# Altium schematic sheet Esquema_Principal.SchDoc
size A4
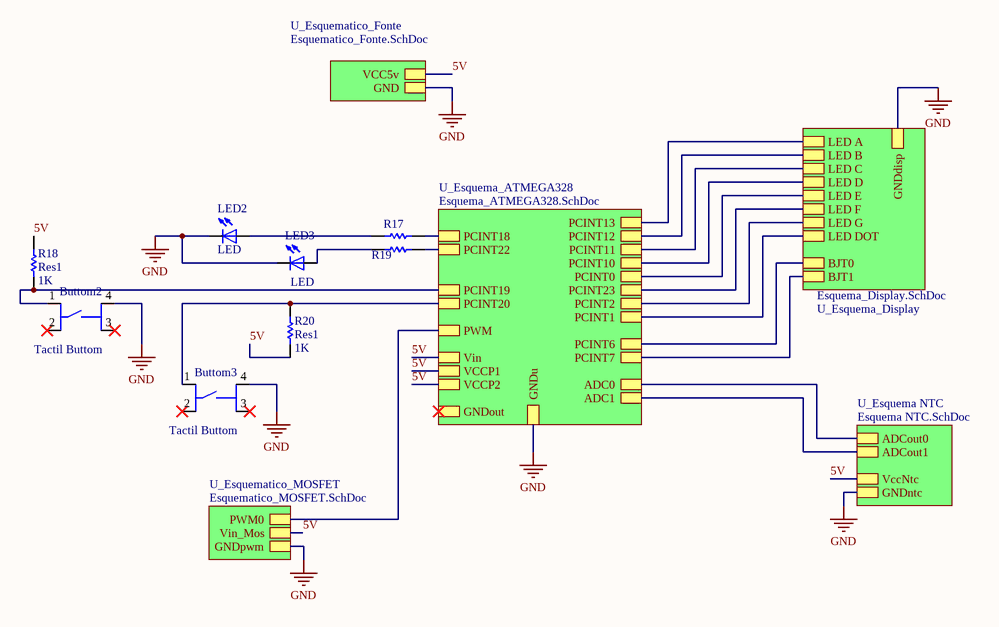
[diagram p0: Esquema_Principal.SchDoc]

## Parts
Buttom2  Tactil Buttom  [Tactil Buttom]
Buttom3  Tactil Buttom  [Tactil Buttom]
LED2  LED  [Led_THT]
LED3  LED  [Led_THT]
R17  Res1  [AXIAL-0.3]  (value not drawn)
R18  Res1  value 1K  [AXIAL-0.3]
R19  Res1  [AXIAL-0.3]  (value not drawn)
R20  Res1  value 1K  [AXIAL-0.3]

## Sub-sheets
U_Esquema NTC = Esquema NTC.SchDoc: ADCout0, ADCout1, GNDntc, VccNtc
U_Esquema_ATMEGA328 = Esquema_ATMEGA328.SchDoc: Vin, PCINT18, PCINT19, PCINT6, PCINT7, PWM, PCINT22, PCINT23, PCINT0, PCINT13, PCINT12, PCINT11, PCINT10, ADC1, ADC0, GNDout, PCINT2, PCINT1, PCINT20, VCCP1, VCCP2, GNDu
U_Esquema_Display = Esquema_Display.SchDoc: BJT0, BJT1, LED A, LED B, LED C, LED D, LED E, LED F, LED G, LED DOT, GNDdisp
U_Esquematico_Fonte = Esquematico_Fonte.SchDoc: VCC5v, GND
U_Esquematico_MOSFET = Esquematico_MOSFET.SchDoc: PWM0, Vin_Mos, GNDpwm

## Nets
GND: Buttom2.4 Buttom3.4 LED2.K(C) LED3.K(C) ; sheet U_Esquema_ATMEGA328/GNDu, sheet U_Esquema_Display/GNDdisp, sheet U_Esquematico_Fonte/GND, sheet U_Esquema NTC/GNDntc, sheet U_Esquematico_MOSFET/GNDpwm
5V: R18.2 R20.1 ; sheet U_Esquema_ATMEGA328/Vin, sheet U_Esquema_ATMEGA328/VCCP1, sheet U_Esquema_ATMEGA328/VCCP2, sheet U_Esquematico_Fonte/VCC5v, sheet U_Esquema NTC/VccNtc, sheet U_Esquematico_MOSFET/Vin_Mos
NetButtom2_1: Buttom2.1 R18.1 ; sheet U_Esquema_ATMEGA328/PCINT19
NetButtom3_1: Buttom3.1 R20.2 ; sheet U_Esquema_ATMEGA328/PCINT20
NetLED2_A: LED2.A R17.1
NetLED3_A: LED3.A R19.1
NetR17_2: R17.2 ; sheet U_Esquema_ATMEGA328/PCINT18
NetR19_2: R19.2 ; sheet U_Esquema_ATMEGA328/PCINT22
(unnamed): sheet U_Esquema_ATMEGA328/PCINT6, sheet U_Esquema_Display/BJT0
(unnamed): sheet U_Esquema_ATMEGA328/PCINT7, sheet U_Esquema_Display/BJT1  [a separate net that carries the same name]
(unnamed): sheet U_Esquema_ATMEGA328/PWM, sheet U_Esquematico_MOSFET/PWM0  [a separate net that carries the same name]
(unnamed): sheet U_Esquema_ATMEGA328/PCINT23, sheet U_Esquema_Display/LED F  [a separate net that carries the same name]
(unnamed): sheet U_Esquema_ATMEGA328/PCINT0, sheet U_Esquema_Display/LED E  [a separate net that carries the same name]
(unnamed): sheet U_Esquema_ATMEGA328/PCINT13, sheet U_Esquema_Display/LED A  [a separate net that carries the same name]
(unnamed): sheet U_Esquema_ATMEGA328/PCINT12, sheet U_Esquema_Display/LED B  [a separate net that carries the same name]
(unnamed): sheet U_Esquema_ATMEGA328/PCINT11, sheet U_Esquema_Display/LED C  [a separate net that carries the same name]
(unnamed): sheet U_Esquema_ATMEGA328/PCINT10, sheet U_Esquema_Display/LED D  [a separate net that carries the same name]
(unnamed): sheet U_Esquema_ATMEGA328/ADC1, sheet U_Esquema NTC/ADCout1  [a separate net that carries the same name]
(unnamed): sheet U_Esquema_ATMEGA328/ADC0, sheet U_Esquema NTC/ADCout0  [a separate net that carries the same name]
(unnamed): sheet U_Esquema_ATMEGA328/PCINT2, sheet U_Esquema_Display/LED G  [a separate net that carries the same name]
(unnamed): sheet U_Esquema_ATMEGA328/PCINT1, sheet U_Esquema_Display/LED DOT  [a separate net that carries the same name]

Not connected (* = marked no-connect by the designer): Buttom2 2* 3*; Buttom3 2* 3*

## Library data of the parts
R17 R19 = Res1: Resistor; Value: 1K
R18 R20 = Res1: Resistor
